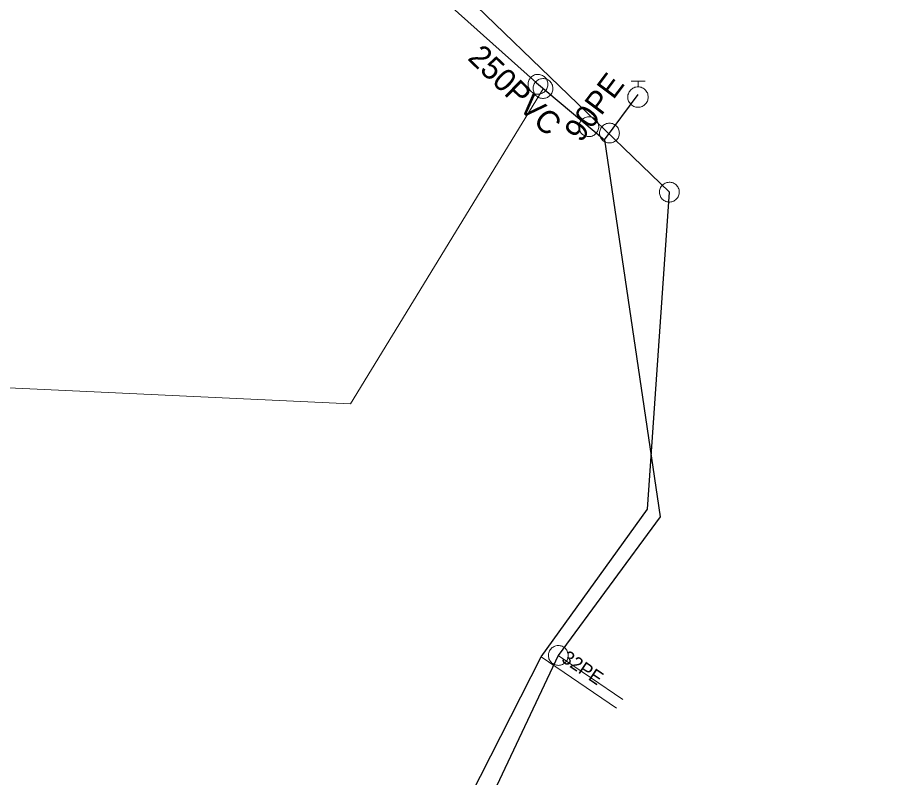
# Model space of a CAD drawing. Extents: x -741806 to -738704, y -1059275 to -1055387.
# Drawn here: x -740375.41 to -740336.28, y -1057662.05 to -1057628.52 of the extents above; entities that cross this region are included whole.
import ezdxf

# ---------------------------------------------------------------- set-up
doc = ezdxf.new("R2010")
doc.units = 0
doc.header["$LTSCALE"] = 0.4
for name, color, linetype, lineweight in [('2', 7, 'Continuous', 25), ('21', 7, 'Continuous', 13), ('3', 7, 'Continuous', 13), ('50', 7, 'Continuous', 13), ('51', 7, 'Continuous', 13), ('52', 7, 'Continuous', 25), ('56', 7, 'Continuous', 13)]:
    doc.layers.add(name, color=color, linetype=linetype, lineweight=lineweight)
for name, color, linetype in [('5', 7, 'Continuous'), ('53', 7, 'Continuous'), ('55', 7, 'Continuous')]:
    doc.layers.add(name, color=color, linetype=linetype)

msp = doc.modelspace()

# ---------------------------------------------------------------- linework, layer by layer
at = {"layer": '2'}
msp.add_line((-740346.649, -1057636.22), (-740359.21, -1057624.09), dxfattribs=at)
msp.add_lwpolyline([(-740338.859, -1057698.61), (-740338.671, -1057697.012), (-740338.633, -1057696.683), (-740336.84, -1057681.49), (-740349.52, -1057669.47), (-740355.43, -1057662.87), (-740352.309, -1057656.73), (-740347.611, -1057650.21), (-740346.649, -1057636.22)], dxfattribs=at)
at = {"layer": '21'}
msp.add_line((-740351.55, -1057656.669), (-740348.71, -1057658.61), dxfattribs=at)
msp.add_lwpolyline([(-740352.212, -1057631.655), (-740360.717, -1057645.567), (-740404.449, -1057643.512), (-740407.789, -1057643.32), (-740408.495, -1057650.898)], dxfattribs=at)
at = {"layer": '3'}
msp.add_lwpolyline([(-740346.618, -1057635.783), (-740346.663, -1057635.782), (-740346.708, -1057635.786), (-740346.754, -1057635.795), (-740346.797, -1057635.808), (-740346.84, -1057635.826), (-740346.88, -1057635.849), (-740346.917, -1057635.875), (-740346.952, -1057635.905), (-740346.983, -1057635.939), (-740347.01, -1057635.975), (-740347.034, -1057636.015), (-740347.054, -1057636.056), (-740347.068, -1057636.099), (-740347.079, -1057636.144), (-740347.084, -1057636.19), (-740347.085, -1057636.236), (-740347.08, -1057636.281), (-740347.072, -1057636.326), (-740347.058, -1057636.37), (-740347.04, -1057636.412), (-740347.018, -1057636.452), (-740346.992, -1057636.489), (-740346.962, -1057636.524), (-740346.929, -1057636.555), (-740346.891, -1057636.583), (-740346.852, -1057636.605), (-740346.811, -1057636.625), (-740346.767, -1057636.64), (-740346.723, -1057636.65), (-740346.677, -1057636.656), (-740346.632, -1057636.657), (-740346.587, -1057636.653), (-740346.541, -1057636.644), (-740346.497, -1057636.63), (-740346.455, -1057636.613), (-740346.415, -1057636.59), (-740346.378, -1057636.564), (-740346.343, -1057636.533), (-740346.312, -1057636.5), (-740346.285, -1057636.464), (-740346.261, -1057636.425), (-740346.241, -1057636.383), (-740346.226, -1057636.34), (-740346.216, -1057636.295), (-740346.211, -1057636.25), (-740346.21, -1057636.204), (-740346.214, -1057636.158), (-740346.223, -1057636.113), (-740346.237, -1057636.069), (-740346.255, -1057636.027), (-740346.277, -1057635.987), (-740346.303, -1057635.95), (-740346.333, -1057635.915), (-740346.366, -1057635.884), (-740346.404, -1057635.856), (-740346.443, -1057635.833), (-740346.484, -1057635.814), (-740346.528, -1057635.799), (-740346.572, -1057635.789), (-740346.617, -1057635.783)], dxfattribs=at)
at = {"layer": '50'}
for p in [(-740348.341, -1057631.318), (-740348.033, -1057631.571), (-740347.722, -1057631.318)]:
    msp.add_line(p, (-740348.033, -1057631.318), dxfattribs=at)
msp.add_lwpolyline([(-740347.585, -1057632.025), (-740347.586, -1057631.976), (-740347.593, -1057631.931), (-740347.605, -1057631.884), (-740347.62, -1057631.841), (-740347.639, -1057631.799), (-740347.666, -1057631.759), (-740347.698, -1057631.724), (-740347.729, -1057631.688), (-740347.766, -1057631.657), (-740347.807, -1057631.633), (-740347.848, -1057631.611), (-740347.89, -1057631.592), (-740347.936, -1057631.583), (-740347.983, -1057631.574), (-740348.029, -1057631.571), (-740348.074, -1057631.574), (-740348.122, -1057631.578), (-740348.169, -1057631.592), (-740348.211, -1057631.61), (-740348.256, -1057631.63), (-740348.294, -1057631.655), (-740348.332, -1057631.685), (-740348.365, -1057631.719), (-740348.394, -1057631.754), (-740348.421, -1057631.793), (-740348.442, -1057631.834), (-740348.459, -1057631.879), (-740348.475, -1057631.924), (-740348.479, -1057631.971), (-740348.484, -1057632.017), (-740348.482, -1057632.066), (-740348.475, -1057632.113), (-740348.463, -1057632.156), (-740348.447, -1057632.202), (-740348.424, -1057632.243), (-740348.401, -1057632.283), (-740348.369, -1057632.319), (-740348.338, -1057632.353), (-740348.3, -1057632.384), (-740348.262, -1057632.409), (-740348.217, -1057632.431), (-740348.175, -1057632.447), (-740348.131, -1057632.461), (-740348.082, -1057632.469), (-740348.035, -1057632.472), (-740347.988, -1057632.469), (-740347.944, -1057632.461), (-740347.898, -1057632.449), (-740347.853, -1057632.433), (-740347.81, -1057632.411), (-740347.771, -1057632.387), (-740347.734, -1057632.357), (-740347.701, -1057632.325), (-740347.672, -1057632.289), (-740347.647, -1057632.248), (-740347.621, -1057632.207), (-740347.606, -1057632.164), (-740347.594, -1057632.117), (-740347.586, -1057632.072)], close=True, dxfattribs=at)
at = {"layer": '51'}
for points in [[(-740352.115, -1057631.736), (-740352.087, -1057631.7), (-740352.064, -1057631.661), (-740352.044, -1057631.619), (-740352.029, -1057631.577), (-740352.019, -1057631.532), (-740352.013, -1057631.486), (-740352.013, -1057631.44), (-740352.017, -1057631.394), (-740352.026, -1057631.35), (-740352.039, -1057631.306), (-740352.057, -1057631.264), (-740352.079, -1057631.223), (-740352.106, -1057631.186), (-740352.136, -1057631.152), (-740352.17, -1057631.121), (-740352.206, -1057631.093), (-740352.245, -1057631.069), (-740352.287, -1057631.05), (-740352.331, -1057631.036), (-740352.375, -1057631.025), (-740352.421, -1057631.02), (-740352.466, -1057631.019), (-740352.512, -1057631.023), (-740352.557, -1057631.032), (-740352.601, -1057631.046), (-740352.643, -1057631.064), (-740352.682, -1057631.086), (-740352.721, -1057631.112), (-740352.755, -1057631.142), (-740352.787, -1057631.176), (-740352.813, -1057631.212), (-740352.837, -1057631.251), (-740352.856, -1057631.293), (-740352.871, -1057631.336), (-740352.881, -1057631.381), (-740352.887, -1057631.427), (-740352.887, -1057631.472), (-740352.884, -1057631.518), (-740352.874, -1057631.563), (-740352.861, -1057631.606), (-740352.843, -1057631.649), (-740352.821, -1057631.689), (-740352.794, -1057631.726), (-740352.765, -1057631.761), (-740352.731, -1057631.792), (-740352.694, -1057631.82), (-740352.654, -1057631.843), (-740352.614, -1057631.862), (-740352.57, -1057631.877), (-740352.525, -1057631.887), (-740352.48, -1057631.892), (-740352.434, -1057631.894), (-740352.388, -1057631.889), (-740352.344, -1057631.881), (-740352.299, -1057631.867), (-740352.257, -1057631.849), (-740352.218, -1057631.827), (-740352.18, -1057631.8), (-740352.146, -1057631.77), (-740352.115, -1057631.737)], [(-740351.89, -1057631.924), (-740351.862, -1057631.888), (-740351.839, -1057631.849), (-740351.819, -1057631.807), (-740351.804, -1057631.765), (-740351.794, -1057631.72), (-740351.788, -1057631.674), (-740351.788, -1057631.628), (-740351.792, -1057631.582), (-740351.801, -1057631.538), (-740351.814, -1057631.494), (-740351.832, -1057631.452), (-740351.854, -1057631.411), (-740351.881, -1057631.374), (-740351.911, -1057631.34), (-740351.945, -1057631.309), (-740351.981, -1057631.281), (-740352.02, -1057631.257), (-740352.062, -1057631.238), (-740352.106, -1057631.224), (-740352.15, -1057631.213), (-740352.196, -1057631.208), (-740352.241, -1057631.207), (-740352.287, -1057631.211), (-740352.332, -1057631.22), (-740352.376, -1057631.234), (-740352.418, -1057631.252), (-740352.457, -1057631.274), (-740352.496, -1057631.3), (-740352.53, -1057631.33), (-740352.562, -1057631.364), (-740352.588, -1057631.4), (-740352.612, -1057631.439), (-740352.631, -1057631.481), (-740352.646, -1057631.524), (-740352.656, -1057631.569), (-740352.662, -1057631.615), (-740352.662, -1057631.66), (-740352.659, -1057631.706), (-740352.649, -1057631.751), (-740352.636, -1057631.794), (-740352.618, -1057631.837), (-740352.596, -1057631.877), (-740352.569, -1057631.914), (-740352.54, -1057631.949), (-740352.506, -1057631.98), (-740352.469, -1057632.008), (-740352.429, -1057632.031), (-740352.389, -1057632.05), (-740352.345, -1057632.065), (-740352.3, -1057632.075), (-740352.255, -1057632.08), (-740352.209, -1057632.082), (-740352.163, -1057632.077), (-740352.119, -1057632.069), (-740352.074, -1057632.055), (-740352.032, -1057632.037), (-740351.993, -1057632.015), (-740351.955, -1057631.988), (-740351.921, -1057631.958), (-740351.89, -1057631.925)], [(-740349.871, -1057633.611), (-740349.843, -1057633.575), (-740349.82, -1057633.536), (-740349.8, -1057633.494), (-740349.785, -1057633.452), (-740349.775, -1057633.407), (-740349.769, -1057633.361), (-740349.769, -1057633.315), (-740349.773, -1057633.269), (-740349.782, -1057633.225), (-740349.795, -1057633.181), (-740349.813, -1057633.139), (-740349.835, -1057633.098), (-740349.862, -1057633.061), (-740349.892, -1057633.027), (-740349.926, -1057632.996), (-740349.962, -1057632.968), (-740350.001, -1057632.944), (-740350.043, -1057632.925), (-740350.087, -1057632.911), (-740350.131, -1057632.9), (-740350.177, -1057632.895), (-740350.222, -1057632.894), (-740350.268, -1057632.898), (-740350.313, -1057632.907), (-740350.357, -1057632.921), (-740350.399, -1057632.939), (-740350.438, -1057632.961), (-740350.477, -1057632.987), (-740350.511, -1057633.017), (-740350.543, -1057633.051), (-740350.569, -1057633.087), (-740350.593, -1057633.126), (-740350.612, -1057633.168), (-740350.627, -1057633.211), (-740350.637, -1057633.256), (-740350.643, -1057633.302), (-740350.643, -1057633.347), (-740350.64, -1057633.393), (-740350.63, -1057633.438), (-740350.617, -1057633.481), (-740350.599, -1057633.524), (-740350.577, -1057633.564), (-740350.55, -1057633.601), (-740350.521, -1057633.636), (-740350.487, -1057633.667), (-740350.45, -1057633.695), (-740350.41, -1057633.718), (-740350.37, -1057633.737), (-740350.326, -1057633.752), (-740350.281, -1057633.762), (-740350.236, -1057633.767), (-740350.19, -1057633.769), (-740350.144, -1057633.764), (-740350.1, -1057633.756), (-740350.055, -1057633.742), (-740350.013, -1057633.724), (-740349.974, -1057633.702), (-740349.936, -1057633.675), (-740349.902, -1057633.645), (-740349.871, -1057633.612)], [(-740348.857, -1057633.611), (-740348.858, -1057633.566), (-740348.866, -1057633.521), (-740348.878, -1057633.476), (-740348.894, -1057633.434), (-740348.915, -1057633.393), (-740348.94, -1057633.354), (-740348.969, -1057633.319), (-740349.001, -1057633.286), (-740349.037, -1057633.258), (-740349.075, -1057633.233), (-740349.116, -1057633.212), (-740349.159, -1057633.195), (-740349.203, -1057633.183), (-740349.248, -1057633.176), (-740349.294, -1057633.174), (-740349.34, -1057633.176), (-740349.385, -1057633.183), (-740349.429, -1057633.195), (-740349.472, -1057633.212), (-740349.513, -1057633.233), (-740349.551, -1057633.258), (-740349.587, -1057633.286), (-740349.619, -1057633.319), (-740349.648, -1057633.354), (-740349.673, -1057633.393), (-740349.694, -1057633.434), (-740349.71, -1057633.476), (-740349.722, -1057633.521), (-740349.729, -1057633.566), (-740349.732, -1057633.612), (-740349.729, -1057633.657), (-740349.722, -1057633.702), (-740349.71, -1057633.747), (-740349.694, -1057633.789), (-740349.673, -1057633.83), (-740349.648, -1057633.869), (-740349.619, -1057633.904), (-740349.587, -1057633.937), (-740349.551, -1057633.965), (-740349.513, -1057633.99), (-740349.472, -1057634.011), (-740349.429, -1057634.028), (-740349.385, -1057634.039), (-740349.34, -1057634.047), (-740349.294, -1057634.049), (-740349.248, -1057634.047), (-740349.203, -1057634.039), (-740349.159, -1057634.028), (-740349.116, -1057634.011), (-740349.075, -1057633.99), (-740349.037, -1057633.965), (-740349.001, -1057633.937), (-740348.969, -1057633.904), (-740348.94, -1057633.869), (-740348.915, -1057633.83), (-740348.894, -1057633.789), (-740348.878, -1057633.747), (-740348.866, -1057633.702), (-740348.858, -1057633.657), (-740348.857, -1057633.612)], [(-740351.189, -1057656.915), (-740351.165, -1057656.877), (-740351.146, -1057656.836), (-740351.13, -1057656.792), (-740351.12, -1057656.748), (-740351.114, -1057656.703), (-740351.113, -1057656.656), (-740351.117, -1057656.611), (-740351.125, -1057656.566), (-740351.138, -1057656.522), (-740351.156, -1057656.48), (-740351.178, -1057656.44), (-740351.204, -1057656.402), (-740351.233, -1057656.367), (-740351.266, -1057656.336), (-740351.303, -1057656.308), (-740351.342, -1057656.284), (-740351.384, -1057656.264), (-740351.427, -1057656.249), (-740351.472, -1057656.239), (-740351.517, -1057656.233), (-740351.563, -1057656.232), (-740351.608, -1057656.235), (-740351.653, -1057656.244), (-740351.697, -1057656.257), (-740351.74, -1057656.275), (-740351.78, -1057656.297), (-740351.817, -1057656.323), (-740351.852, -1057656.353), (-740351.884, -1057656.386), (-740351.912, -1057656.423), (-740351.935, -1057656.462), (-740351.955, -1057656.503), (-740351.97, -1057656.547), (-740351.98, -1057656.59), (-740351.986, -1057656.636), (-740351.988, -1057656.682), (-740351.983, -1057656.728), (-740351.976, -1057656.773), (-740351.962, -1057656.816), (-740351.944, -1057656.858), (-740351.922, -1057656.899), (-740351.896, -1057656.937), (-740351.866, -1057656.971), (-740351.834, -1057657.003), (-740351.797, -1057657.031), (-740351.758, -1057657.055), (-740351.716, -1057657.074), (-740351.674, -1057657.089), (-740351.628, -1057657.1), (-740351.583, -1057657.105), (-740351.537, -1057657.106), (-740351.492, -1057657.103), (-740351.447, -1057657.094), (-740351.403, -1057657.082), (-740351.36, -1057657.064), (-740351.32, -1057657.042), (-740351.283, -1057657.016), (-740351.248, -1057656.985), (-740351.217, -1057656.952), (-740351.189, -1057656.916)]]:
    msp.add_lwpolyline(points, dxfattribs=at)
at = {"layer": '52'}
msp.add_line((-740349.517, -1057633.908), (-740348.02, -1057631.909), dxfattribs=at)
for points in [[(-740503.249, -1057612.745), (-740480.638, -1057607.754), (-740465.682, -1057599.577), (-740452.151, -1057592.668), (-740420.197, -1057586.102), (-740388.602, -1057603.262), (-740371.388, -1057615.413), (-740359.399, -1057625.23), (-740352.519, -1057631.399), (-740349.517, -1057633.908)], [(-740349.517, -1057633.908), (-740347.05, -1057650.55), (-740351.55, -1057656.669), (-740354.649, -1057663.22), (-740349.359, -1057668.59), (-740336.28, -1057680.86), (-740338.094, -1057696.362), (-740338.156, -1057696.886), (-740338.199, -1057697.254), (-740337.96, -1057698.37), (-740338.05, -1057698.96)]]:
    msp.add_lwpolyline(points, dxfattribs=at)
at = {"layer": '56'}
msp.add_line((-740348.989, -1057658.99), (-740352.309, -1057656.73), dxfattribs=at)

# ---------------------------------------------------------------- texts
at = {"layer": '5'}
msp.add_text('250PVC', height=1, rotation=316, dxfattribs=at).set_placement((-740355.596, -1057630.339))
at = {"layer": '53'}
msp.add_text('90PE', height=1, rotation=53, dxfattribs=at).set_placement((-740350.556, -1057634.068))
at = {"layer": '55'}
msp.add_text('32PE', height=0.6, rotation=326, dxfattribs=at).set_placement((-740351.455, -1057656.91))

doc.saveas('drawing.dxf')
